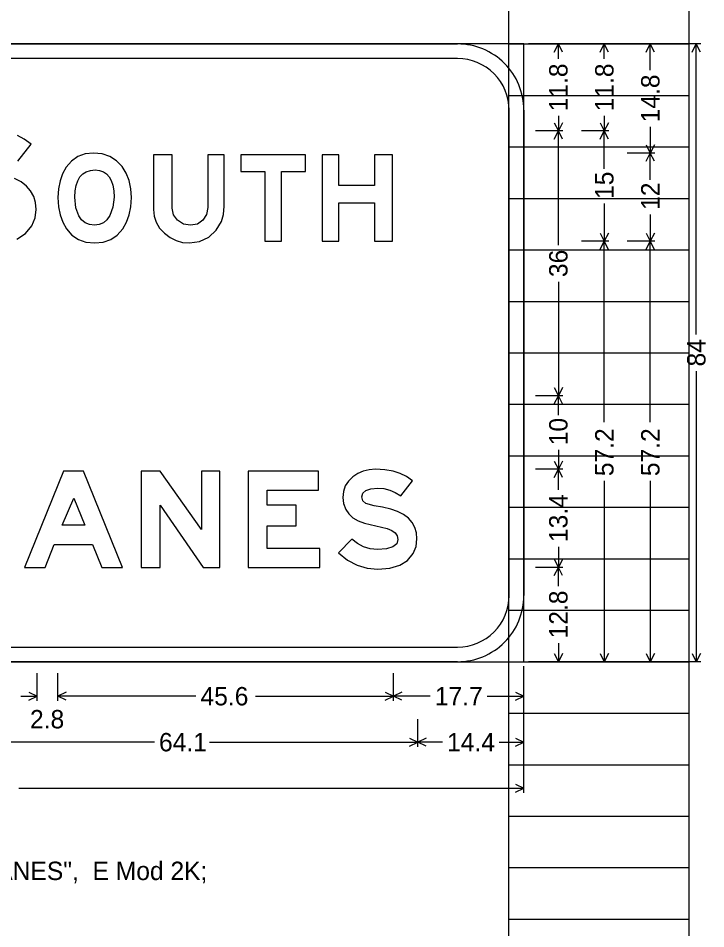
# Model space of a CAD drawing. Extents: x 1820207 to 1820557, y 740216 to 740315.
# Drawn here: x 1820488.544 to 1820492.281, y 740260.489 to 740265.442 of the extents above; entities that cross this region are included whole.
import ezdxf

# ---------------------------------------------------------------- set-up
doc = ezdxf.new("R2010")
doc.units = 0
doc.layers.add('SC_Scratch1', color=7, linetype='Continuous')
doc.layers.add('SC_Scratch3', color=7, linetype='Continuous')

msp = doc.modelspace()

# ---------------------------------------------------------------- linework, layer by layer
at = {"layer": 'SC_Scratch1'}
for p, q in [((1820491.211, 740255.2219), (1820491.211, 740275.3819)), ((1820492.191, 740255.2219), (1820492.191, 740275.3819)), ((1820491.211, 740265.3019), (1820492.191, 740265.3019)), ((1820491.211, 740265.0219), (1820492.191, 740265.0219)), ((1820491.211, 740264.7419), (1820492.191, 740264.7419)), ((1820491.211, 740264.4619), (1820492.191, 740264.4619)), ((1820491.211, 740264.1819), (1820492.191, 740264.1819)), ((1820491.211, 740263.9019), (1820492.191, 740263.9019)), ((1820491.211, 740263.6219), (1820492.191, 740263.6219)), ((1820491.211, 740263.3419), (1820492.191, 740263.3419)), ((1820491.211, 740263.0619), (1820492.191, 740263.0619)), ((1820491.211, 740262.7819), (1820492.191, 740262.7819)), ((1820491.211, 740262.5019), (1820492.191, 740262.5019)), ((1820491.211, 740262.2219), (1820492.191, 740262.2219)), ((1820491.211, 740261.9419), (1820492.191, 740261.9419)), ((1820491.211, 740261.6619), (1820492.191, 740261.6619)), ((1820491.211, 740261.3819), (1820492.191, 740261.3819)), ((1820491.211, 740261.1019), (1820492.191, 740261.1019)), ((1820491.211, 740260.8219), (1820492.191, 740260.8219)), ((1820491.211, 740260.5419), (1820492.191, 740260.5419))]:
    msp.add_line(p, q, dxfattribs=at)
at = {"layer": 'SC_Scratch3'}
for p, q in [((1820492.2546, 740265.3019), (1820491.3171, 740265.3019)), ((1820491.5046, 740265.3019), (1820491.3546, 740265.3019)), ((1820491.4572, 740265.2572), (1820491.4796, 740265.3019)), ((1820491.4796, 740265.2201), (1820491.4796, 740265.3019)), ((1820491.502, 740265.2572), (1820491.4796, 740265.3019)), ((1820491.7546, 740265.3019), (1820491.6046, 740265.3019)), ((1820491.7072, 740265.2572), (1820491.7296, 740265.3019)), ((1820491.7296, 740265.2201), (1820491.7296, 740265.3019)), ((1820491.752, 740265.2572), (1820491.7296, 740265.3019)), ((1820492.0046, 740265.3019), (1820491.8546, 740265.3019)), ((1820491.9572, 740265.2572), (1820491.9796, 740265.3019)), ((1820491.9796, 740265.1601), (1820491.9796, 740265.3019)), ((1820492.002, 740265.2572), (1820491.9796, 740265.3019)), ((1820492.2072, 740265.2572), (1820492.2296, 740265.3019)), ((1820492.2296, 740263.721), (1820492.2296, 740265.3019)), ((1820492.252, 740265.2572), (1820492.2296, 740265.3019)), ((1820491.4572, 740264.8733), (1820491.4796, 740264.8286)), ((1820491.4796, 740264.9104), (1820491.4796, 740264.8286)), ((1820491.502, 740264.8733), (1820491.4796, 740264.8286)), ((1820491.7072, 740264.8733), (1820491.7296, 740264.8286)), ((1820491.7296, 740264.9104), (1820491.7296, 740264.8286)), ((1820491.752, 740264.8733), (1820491.7296, 740264.8286)), ((1820491.5046, 740264.8286), (1820491.3546, 740264.8286)), ((1820491.4572, 740264.7839), (1820491.4796, 740264.8286)), ((1820491.4796, 740264.2082), (1820491.4796, 740264.8286)), ((1820491.502, 740264.7839), (1820491.4796, 740264.8286)), ((1820491.7546, 740264.8286), (1820491.6046, 740264.8286)), ((1820491.7072, 740264.7839), (1820491.7296, 740264.8286)), ((1820491.7296, 740264.6232), (1820491.7296, 740264.8286)), ((1820491.752, 740264.7839), (1820491.7296, 740264.8286)), ((1820491.9796, 740264.8504), (1820491.9796, 740264.7086)), ((1820491.9572, 740264.7533), (1820491.9796, 740264.7086)), ((1820492.002, 740264.7533), (1820491.9796, 740264.7086)), ((1820492.0046, 740264.7086), (1820491.8546, 740264.7086)), ((1820491.9572, 740264.6639), (1820491.9796, 740264.7086)), ((1820491.9796, 740264.5627), (1820491.9796, 740264.7086)), ((1820492.002, 740264.6639), (1820491.9796, 740264.7086)), ((1820491.7296, 740264.4339), (1820491.7296, 740264.2286)), ((1820491.9796, 740264.3745), (1820491.9796, 740264.2286)), ((1820491.7546, 740264.2286), (1820491.6046, 740264.2286)), ((1820491.7546, 740264.2286), (1820491.6046, 740264.2286)), ((1820491.7072, 740264.2733), (1820491.7296, 740264.2286)), ((1820491.7072, 740264.1839), (1820491.7296, 740264.2286)), ((1820491.752, 740264.2733), (1820491.7296, 740264.2286)), ((1820491.7296, 740263.2443), (1820491.7296, 740264.2286)), ((1820491.752, 740264.1839), (1820491.7296, 740264.2286)), ((1820492.0046, 740264.2286), (1820491.8546, 740264.2286)), ((1820492.0046, 740264.2286), (1820491.8546, 740264.2286)), ((1820491.9572, 740264.2733), (1820491.9796, 740264.2286)), ((1820491.9572, 740264.1839), (1820491.9796, 740264.2286)), ((1820492.002, 740264.2733), (1820491.9796, 740264.2286)), ((1820491.9796, 740263.2443), (1820491.9796, 740264.2286)), ((1820492.002, 740264.1839), (1820491.9796, 740264.2286)), ((1820491.4796, 740264.0089), (1820491.4796, 740263.3886)), ((1820492.2296, 740263.5228), (1820492.2296, 740261.9419)), ((1820491.5046, 740263.3886), (1820491.3546, 740263.3886)), ((1820491.4572, 740263.4333), (1820491.4796, 740263.3886)), ((1820491.4572, 740263.3439), (1820491.4796, 740263.3886)), ((1820491.502, 740263.4333), (1820491.4796, 740263.3886)), ((1820491.4796, 740263.2829), (1820491.4796, 740263.3886)), ((1820491.502, 740263.3439), (1820491.4796, 740263.3886)), ((1820491.4796, 740263.0942), (1820491.4796, 740262.9886)), ((1820491.4572, 740263.0333), (1820491.4796, 740262.9886)), ((1820491.502, 740263.0333), (1820491.4796, 740262.9886)), ((1820491.5046, 740262.9886), (1820491.3546, 740262.9886)), ((1820491.4572, 740262.9439), (1820491.4796, 740262.9886)), ((1820491.4796, 740262.8762), (1820491.4796, 740262.9886)), ((1820491.502, 740262.9439), (1820491.4796, 740262.9886)), ((1820491.7296, 740262.9262), (1820491.7296, 740261.9419)), ((1820491.9796, 740262.9262), (1820491.9796, 740261.9419)), ((1820491.4796, 740262.5676), (1820491.4796, 740262.4552)), ((1820491.4572, 740262.4999), (1820491.4796, 740262.4552)), ((1820491.502, 740262.4999), (1820491.4796, 740262.4552)), ((1820491.5046, 740262.4552), (1820491.3546, 740262.4552)), ((1820491.5046, 740262.4552), (1820491.3546, 740262.4552)), ((1820491.4572, 740262.4105), (1820491.4796, 740262.4552)), ((1820491.4796, 740262.3534), (1820491.4796, 740262.4552)), ((1820491.502, 740262.4105), (1820491.4796, 740262.4552)), ((1820491.4796, 740262.0437), (1820491.4796, 740261.9419)), ((1820491.4572, 740261.9866), (1820491.4796, 740261.9419)), ((1820491.502, 740261.9866), (1820491.4796, 740261.9419)), ((1820491.7072, 740261.9866), (1820491.7296, 740261.9419)), ((1820491.752, 740261.9866), (1820491.7296, 740261.9419)), ((1820491.9572, 740261.9866), (1820491.9796, 740261.9419)), ((1820492.002, 740261.9866), (1820491.9796, 740261.9419)), ((1820492.2072, 740261.9866), (1820492.2296, 740261.9419)), ((1820492.252, 740261.9866), (1820492.2296, 740261.9419)), ((1820491.2921, 740261.2294), (1820491.2921, 740261.9169)), ((1820492.2546, 740261.9419), (1820491.3171, 740261.9419)), ((1820491.5046, 740261.9419), (1820491.3546, 740261.9419)), ((1820491.7546, 740261.9419), (1820491.6046, 740261.9419)), ((1820492.0046, 740261.9419), (1820491.8546, 740261.9419)), ((1820488.6464, 740261.7294), (1820488.6464, 740261.8794)), ((1820488.7598, 740261.7294), (1820488.7598, 740261.8794)), ((1820490.5838, 740261.7294), (1820490.5838, 740261.8794)), ((1820490.5838, 740261.7294), (1820490.5838, 740261.8794)), ((1820491.2921, 740261.7294), (1820491.2921, 740261.8794)), ((1820488.5577, 740261.7544), (1820488.6464, 740261.7544)), ((1820488.6017, 740261.7768), (1820488.6464, 740261.7544)), ((1820488.6017, 740261.732), (1820488.6464, 740261.7544)), ((1820488.8045, 740261.7768), (1820488.7598, 740261.7544)), ((1820489.5096, 740261.7544), (1820488.7598, 740261.7544)), ((1820488.8045, 740261.732), (1820488.7598, 740261.7544)), ((1820489.834, 740261.7544), (1820490.5838, 740261.7544)), ((1820490.5391, 740261.7768), (1820490.5838, 740261.7544)), ((1820490.5391, 740261.732), (1820490.5838, 740261.7544)), ((1820490.6285, 740261.7768), (1820490.5838, 740261.7544)), ((1820490.7834, 740261.7544), (1820490.5838, 740261.7544)), ((1820490.6285, 740261.732), (1820490.5838, 740261.7544)), ((1820491.0925, 740261.7544), (1820491.2921, 740261.7544)), ((1820491.2474, 740261.7768), (1820491.2921, 740261.7544)), ((1820491.2474, 740261.732), (1820491.2921, 740261.7544)), ((1820490.7161, 740261.4794), (1820490.7161, 740261.6294)), ((1820490.7161, 740261.4794), (1820490.7161, 740261.6294)), ((1820491.2921, 740261.4794), (1820491.2921, 740261.6294)), ((1820490.6714, 740261.5268), (1820490.7161, 740261.5044)), ((1820490.7608, 740261.5268), (1820490.7161, 740261.5044)), ((1820491.2474, 740261.5268), (1820491.2921, 740261.5044)), ((1820489.2838, 740261.5044), (1820488.1508, 740261.5044)), ((1820489.583, 740261.5044), (1820490.7161, 740261.5044)), ((1820490.6714, 740261.482), (1820490.7161, 740261.5044)), ((1820490.8498, 740261.5044), (1820490.7161, 740261.5044)), ((1820490.7608, 740261.482), (1820490.7161, 740261.5044)), ((1820491.1584, 740261.5044), (1820491.2921, 740261.5044)), ((1820491.2474, 740261.482), (1820491.2921, 740261.5044)), ((1820491.2474, 740261.2768), (1820491.2921, 740261.2544)), ((1820488.5463, 740261.2544), (1820491.2921, 740261.2544)), ((1820491.2474, 740261.232), (1820491.2921, 740261.2544))]:
    msp.add_line(p, q, dxfattribs=at)
for points in [[(1820485.5321, 740261.9419), (1820491.2921, 740261.9419), (1820491.2921, 740265.3019), (1820485.5321, 740265.3019), (1820485.5321, 740261.9419), (1820485.5321, 740261.9419), (1820485.5321, 740261.9419)], [(1820485.8921, 740265.3019), (1820490.9321, 740265.3019)], [(1820490.9321, 740265.2219), (1820485.8921, 740265.2219)], [(1820490.9321, 740265.2219), (1820490.9321, 740265.2219), (1820490.9321, 740265.2219)], [(1820491.2121, 740262.3019), (1820491.2121, 740264.9419)], [(1820491.2921, 740264.9419), (1820491.2921, 740262.3019)], [(1820488.5414, 740264.6652), (1820488.6138, 740264.7573), (1820488.5765, 740264.7837), (1820488.539, 740264.8031)], [(1820488.5363, 740264.241), (1820488.5837, 740264.2711), (1820488.618, 740264.3135), (1820488.6352, 740264.3562), (1820488.641, 740264.4023), (1820488.6376, 740264.4395), (1820488.6279, 740264.473), (1820488.6113, 740264.5028), (1820488.5884, 740264.5291), (1820488.5589, 740264.5514), (1820488.5227, 740264.5702)], [(1820491.2121, 740262.3019), (1820491.2121, 740262.3019), (1820491.2121, 740262.3019)], [(1820485.8921, 740262.0219), (1820490.9321, 740262.0219)], [(1820490.9321, 740261.9419), (1820485.8921, 740261.9419)]]:
    msp.add_lwpolyline(points, dxfattribs=at)
for points in [[(1820489.1586, 740264.4661), (1820489.1554, 740264.5147), (1820489.1461, 740264.5591), (1820489.1305, 740264.599), (1820489.1087, 740264.6346), (1820489.078, 740264.6669), (1820489.0418, 740264.69), (1820489.0001, 740264.7038), (1820488.9531, 740264.7086), (1820488.9077, 740264.7037), (1820488.8678, 740264.6893), (1820488.8335, 740264.6652), (1820488.8049, 740264.6317), (1820488.785, 740264.5962), (1820488.7711, 740264.5569), (1820488.7625, 740264.5134), (1820488.7598, 740264.4661), (1820488.7625, 740264.4165), (1820488.7712, 740264.3718), (1820488.7856, 740264.3317), (1820488.8058, 740264.2962), (1820488.8352, 740264.2625), (1820488.8707, 740264.2385), (1820488.9119, 740264.2241), (1820488.9593, 740264.2194), (1820489.006, 740264.2241), (1820489.0472, 740264.2387), (1820489.0824, 740264.2627), (1820489.112, 740264.2966), (1820489.1322, 740264.3321), (1820489.1469, 740264.3722), (1820489.1556, 740264.4168)], [(1820489.6623, 740264.4193), (1820489.6623, 740264.6993), (1820489.5736, 740264.6993), (1820489.5736, 740264.4132), (1820489.567, 740264.3738), (1820489.5475, 740264.3427), (1820489.5173, 740264.3222), (1820489.4793, 740264.3154), (1820489.4428, 740264.3222), (1820489.4103, 740264.3428), (1820489.3874, 740264.3728), (1820489.3797, 740264.408), (1820489.3797, 740264.6993), (1820489.2782, 740264.6993), (1820489.2782, 740264.4018), (1820489.282, 740264.3655), (1820489.2933, 740264.3318), (1820489.3122, 740264.3005), (1820489.3389, 740264.2721), (1820489.3693, 740264.2489), (1820489.4021, 740264.2325), (1820489.437, 740264.2226), (1820489.4742, 740264.2194), (1820489.5297, 740264.2273), (1820489.5796, 740264.2513), (1820489.6205, 740264.2887), (1820489.649, 740264.3368), (1820489.659, 740264.3738)], [(1820489.8839, 740264.2286), (1820489.9751, 740264.2286), (1820489.9751, 740264.6087), (1820490.1047, 740264.6087), (1820490.1047, 740264.6993), (1820489.7534, 740264.6993), (1820489.7534, 740264.6087), (1820489.8839, 740264.6087)], [(1820490.195, 740264.2286), (1820490.2873, 740264.2286), (1820490.2873, 740264.4369), (1820490.4811, 740264.4369), (1820490.4811, 740264.2286), (1820490.5785, 740264.2286), (1820490.5785, 740264.6993), (1820490.4811, 740264.6993), (1820490.4811, 740264.5315), (1820490.2873, 740264.5315), (1820490.2873, 740264.6993), (1820490.195, 740264.6993)], [(1820489.0644, 740264.4693), (1820489.0588, 740264.4137), (1820489.0422, 740264.3682), (1820489.0262, 740264.3452), (1820489.0069, 740264.329), (1820488.9838, 740264.3191), (1820488.9575, 740264.3159), (1820488.9303, 740264.3191), (1820488.9071, 740264.3287), (1820488.8876, 740264.3445), (1820488.8723, 740264.3668), (1820488.8571, 740264.4112), (1820488.8521, 740264.4678), (1820488.8537, 740264.5025), (1820488.8589, 740264.5327), (1820488.8672, 740264.5581), (1820488.8794, 740264.5792), (1820488.8946, 740264.5953), (1820488.9136, 740264.607), (1820488.9358, 740264.614), (1820488.9614, 740264.6164), (1820488.9855, 740264.6141), (1820489.0064, 740264.6072), (1820489.024, 740264.5956), (1820489.0386, 740264.5796), (1820489.0497, 740264.5588), (1820489.0579, 740264.5336), (1820489.0627, 740264.5036)], [(1820488.5774, 740262.4552), (1820488.6897, 740262.4552), (1820488.7393, 740262.5791), (1820488.9483, 740262.5791), (1820488.9977, 740262.4552), (1820489.1101, 740262.4552), (1820488.8981, 740262.9783), (1820488.7894, 740262.9783)], [(1820489.2121, 740262.4552), (1820489.3146, 740262.4552), (1820489.3146, 740262.7938), (1820489.5496, 740262.4552), (1820489.6393, 740262.4552), (1820489.6393, 740262.9783), (1820489.5403, 740262.9783), (1820489.5403, 740262.6615), (1820489.3146, 740262.9783), (1820489.2121, 740262.9783)], [(1820490.1838, 740262.5578), (1820489.8963, 740262.5578), (1820489.8963, 740262.6808), (1820490.0551, 740262.6808), (1820490.0551, 740262.7936), (1820489.8963, 740262.7936), (1820489.8963, 740262.8757), (1820490.1764, 740262.8757), (1820490.1764, 740262.9783), (1820489.7934, 740262.9783), (1820489.7934, 740262.4552), (1820490.1838, 740262.4552)], [(1820490.2841, 740262.5341), (1820490.3336, 740262.4949), (1820490.386, 740262.4672), (1820490.4409, 740262.4505), (1820490.4988, 740262.445), (1820490.5644, 740262.4503), (1820490.6182, 740262.4662), (1820490.6603, 740262.493), (1820490.6908, 740262.5307), (1820490.7062, 740262.5686), (1820490.7113, 740262.6097), (1820490.7083, 740262.6427), (1820490.6996, 740262.6725), (1820490.6849, 740262.699), (1820490.6645, 740262.7223), (1820490.6383, 740262.7422), (1820490.6062, 740262.7589), (1820490.5682, 740262.7722), (1820490.5246, 740262.7823), (1820490.4783, 740262.7891), (1820490.4339, 740262.8025), (1820490.4172, 740262.8167), (1820490.4118, 740262.8379), (1820490.4171, 740262.8589), (1820490.4334, 740262.874), (1820490.4607, 740262.8831), (1820490.4988, 740262.8861), (1820490.5315, 740262.8834), (1820490.5633, 740262.8754), (1820490.5935, 740262.8619), (1820490.6227, 740262.8433), (1820490.6871, 740262.9252), (1820490.654, 740262.9486), (1820490.6206, 740262.9659), (1820490.5815, 740262.9784), (1820490.5366, 740262.986), (1820490.4862, 740262.9886), (1820490.4512, 740262.986), (1820490.419, 740262.9784), (1820490.3895, 740262.9658), (1820490.3626, 740262.9481), (1820490.3385, 740262.9246), (1820490.3214, 740262.8978), (1820490.3112, 740262.8677), (1820490.3078, 740262.8344), (1820490.3118, 740262.8018), (1820490.3241, 740262.7699), (1820490.3404, 740262.7457), (1820490.3626, 740262.7252), (1820490.3909, 740262.7084), (1820490.4254, 740262.6954), (1820490.5484, 740262.6671), (1820490.5743, 740262.6565), (1820490.593, 740262.6429), (1820490.6041, 740262.6262), (1820490.6079, 740262.6063), (1820490.6009, 740262.5828), (1820490.5799, 740262.5661), (1820490.545, 740262.556), (1820490.4961, 740262.5528), (1820490.4562, 740262.5561), (1820490.42, 740262.5667), (1820490.3871, 740262.5841), (1820490.3579, 740262.6087)], [(1820488.782, 740262.6847), (1820488.8463, 740262.8323), (1820488.9054, 740262.6847)]]:
    msp.add_lwpolyline(points, close=True, dxfattribs=at)
for centre, radius, start, end in [((1820490.9321, 740264.9419), 0.36, 0, 90.0002), ((1820490.9321, 740264.9419), 0.28, 0, 90.0002), ((1820490.9321, 740262.3019), 0.36, 270.0001, 0.0003), ((1820490.9321, 740262.3019), 0.28, 270.0001, 0.0003)]:
    msp.add_arc(centre, radius, start, end, dxfattribs=at)

# ---------------------------------------------------------------- texts
for s, p in [('11.8', (1820491.5296, 740264.9354)), ('11.8', (1820491.7796, 740264.9354)), ('14.8', (1820492.0296, 740264.8754)), ('15', (1820491.7796, 740264.4589)), ('12', (1820492.0296, 740264.3995)), ('36', (1820491.5296, 740264.0339)), ('84', (1820492.2796, 740263.5478)), ('10', (1820491.5296, 740263.1192)), ('57.2', (1820491.7796, 740262.9512)), ('57.2', (1820492.0296, 740262.9512)), ('13.4', (1820491.5296, 740262.5926)), ('12.8', (1820491.5296, 740262.0687))]:
    msp.add_text(s, height=0.1, rotation=90.0002, dxfattribs=at).set_placement(p)
for s, p in [('45.6', (1820489.5346, 740261.7044)), ('17.7', (1820490.8084, 740261.7044)), ('2.8', (1820488.6078, 740261.5794)), ('64.1', (1820489.3088, 740261.4544)), ('14.4', (1820490.8748, 740261.4544)), ('Interstate 77 M1-1; "SOUTH",  E Mod 2K; "ALL LANES",  E Mod 2K;', (1820485.5321, 740260.7544))]:
    msp.add_text(s, height=0.1, dxfattribs=at).set_placement(p)

doc.saveas('drawing.dxf')
